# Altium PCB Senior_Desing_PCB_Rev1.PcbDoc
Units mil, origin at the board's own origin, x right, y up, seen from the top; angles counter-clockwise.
Board outline 6000 x 4000 mil, 2 copper layers (Top Layer, Bottom Layer); 40 components, 31 nets, 152 pads, 0 vias.
Unrouted connection lines stored in the file: 76.
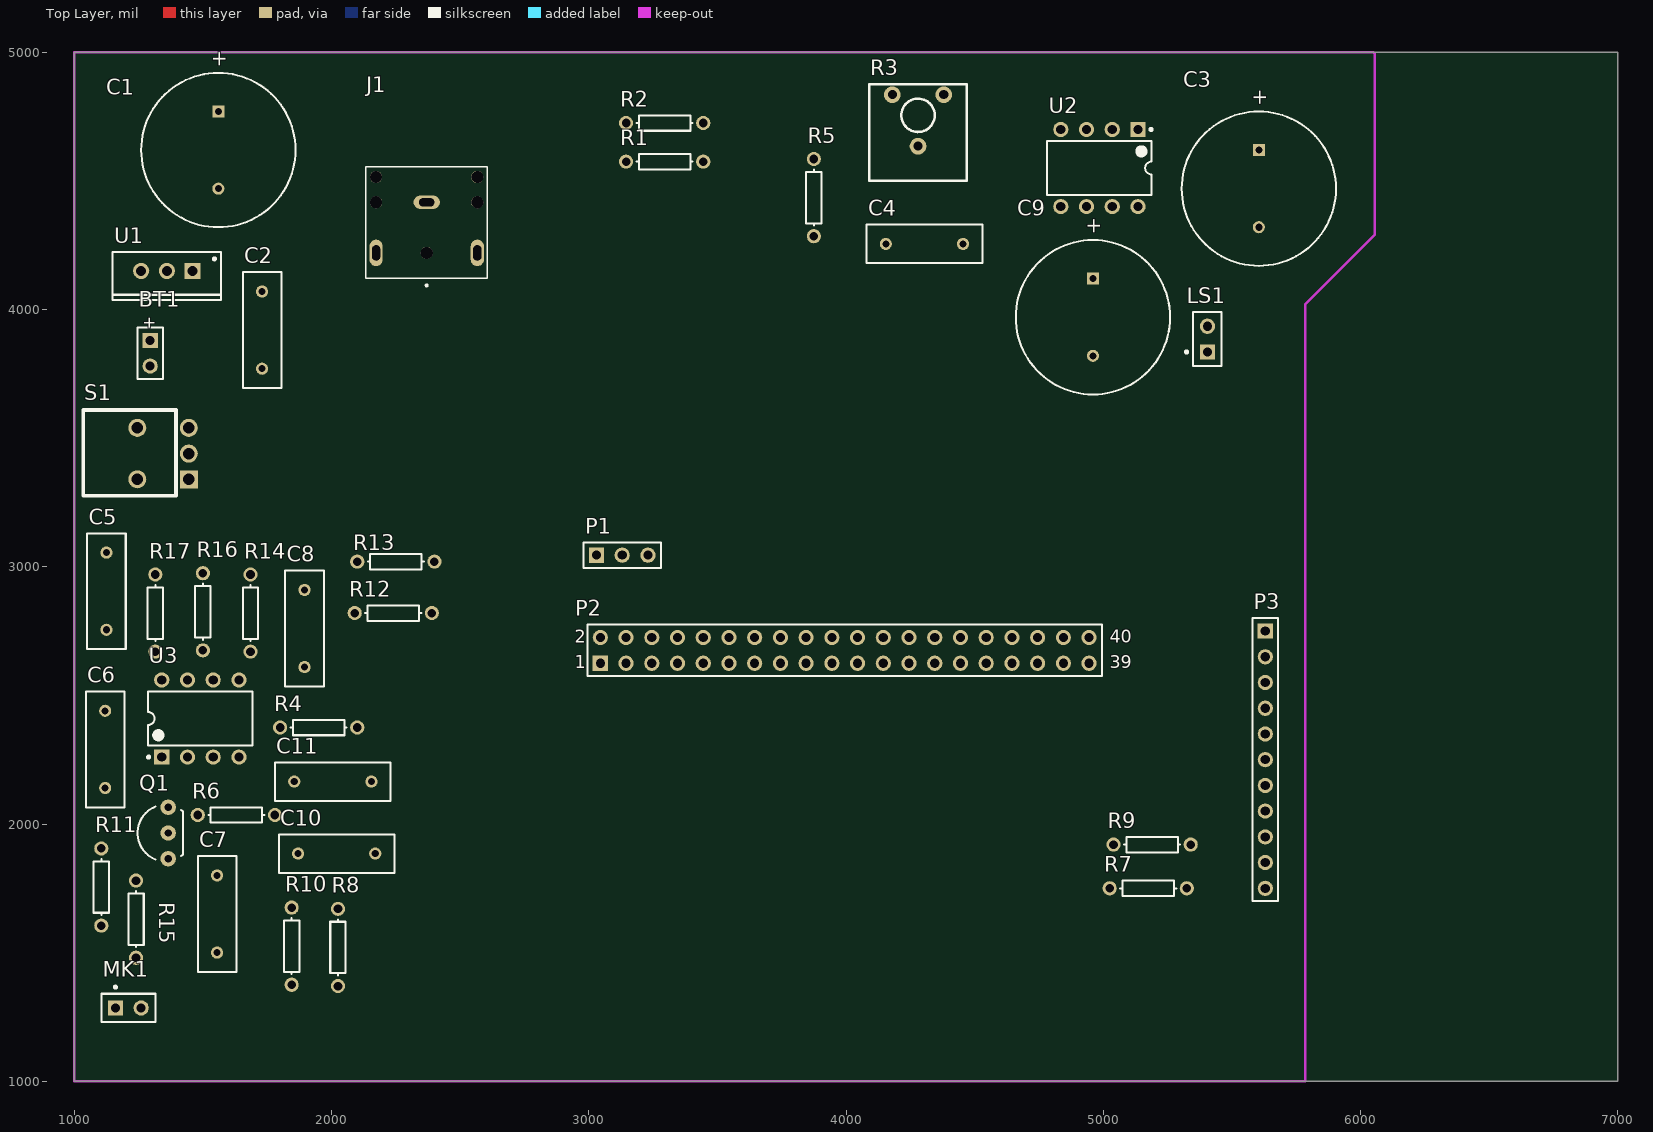
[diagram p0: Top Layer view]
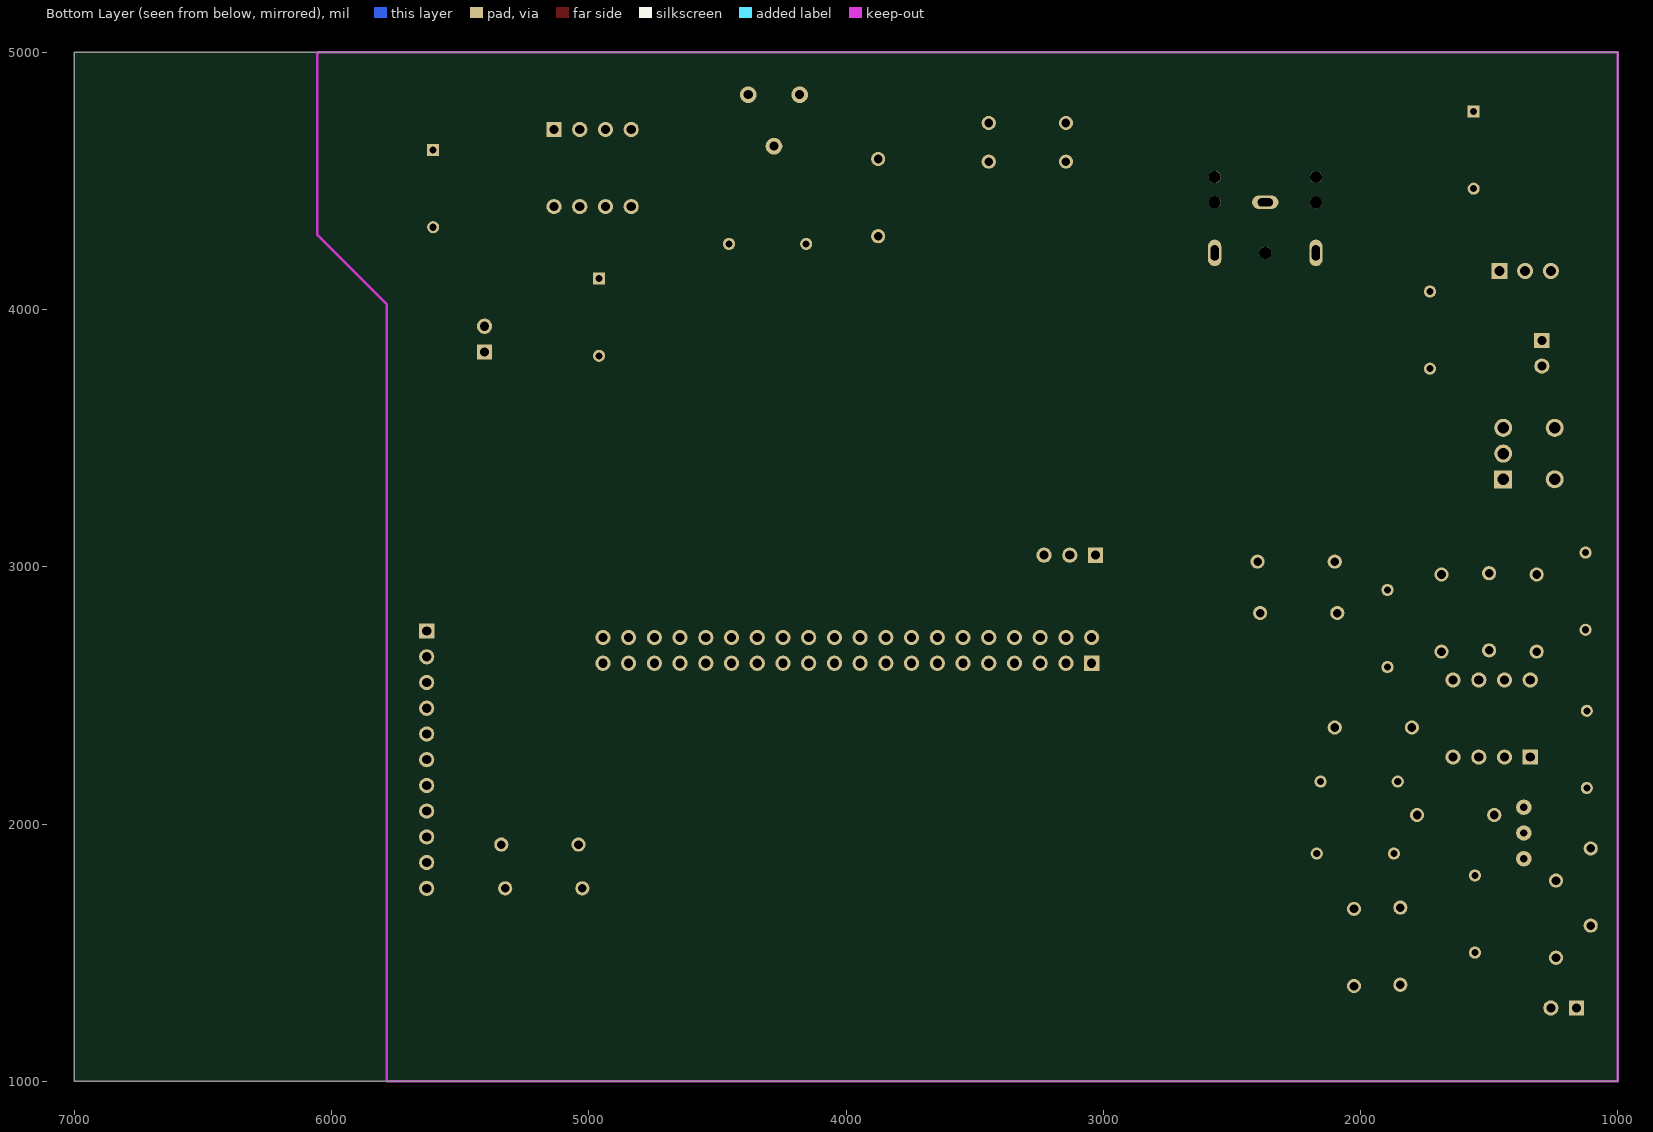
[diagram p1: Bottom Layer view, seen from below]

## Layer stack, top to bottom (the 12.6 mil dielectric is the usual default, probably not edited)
Top Solder: solder mask 0.4, Solder Resist, Dk 3.5
Top Layer: signal copper 1.4
Dielectric 1: dielectric 12.6, FR-4, Dk 4.8
Bottom Layer: signal copper 1.4
Bottom Solder: solder mask 0.4, Solder Resist, Dk 3.5

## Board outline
1000,1000 7000,1000 7000,5000 1000,5000

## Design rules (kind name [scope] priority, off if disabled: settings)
Clearance [All] p1: gap=10 ignorepadtopadclearanceinfootprint=FALSE except(0: Arc-Hole Track-Hole SMDPad-Hole THPad-Hole Via-Hole Fill-Hole Poly-Hole Region-Hole Text-Hole)
PolygonConnect [All] p1: connectstyle=Relief reliefconductorwidth=10 reliefentries=4 polygonreliefangle="90 Angle" airgapwidth=10
RoutingVias [All] p1: holewidth=28 width=50 viastyle="Through Hole" minholewidth=28 minwidth=50 maxholewidth=28 maxwidth=50
SolderMaskExpansion [All] p1: expansion=4 istentingtop=FALSE
Width [All] p1: maxlimit=10 minlimit=10 preferedwidth=10
30 further rules are at their usual default settings.

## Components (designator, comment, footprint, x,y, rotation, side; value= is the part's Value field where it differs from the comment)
BT1 "Battery" BAT-2 1295,3830 r270 top
C1 "Cap Pol1" RB7.6-15 1560,4620 r90 top value=100pF
C2 "Cap" RAD-0.3 1730,3920 r270 top value=0.47uF
C3 "Cap Pol1" RB7.6-15 5605,4470 r90 top value=100uF
C4 "Cap" RAD-0.3 4305,4255 r0 top value=0.05uF
C5 "Cap" RAD-0.3 1125,2905 r90 top value=0.1uF
C6 "Cap" RAD-0.3 1120,2290 r90 top value=0.33uF
C7 "Cap" RAD-0.3 1555,1650 r90 top value=220nF
C8 "Cap" RAD-0.3 1895,2760 r90 top value=220nF
C9 "Cap Pol1" RB7.6-15 4960,3970 r90 top value=220uF
C10 "Cap" RAD-0.3 2020,1885 r0 top value=10uF
C11 "Cap" RAD-0.3 2005,2165 r0 top value=0.1uF
J1 "SJ1-3523N" CUI_SJ1-3523N 2370,4416.85 r180 top
LS1 "Speaker" PIN2 5405,3835 r90 top
MK1 "Mic1" PIN2 1160,1285 r0 top
P1 "Screen" HDR1X3 3030,3045 r0 top
P2 "PI 5" HDR2X20 3045,2625 r0 top
P3 "CODEC WM8731" HDR1X11 5630,2750 r270 top
Q1 "2N3904" TO92C 1365,1865 r180 top
R1 "Res1" AXIAL-0.3 3295,4575 r180 top value=1K
R2 "Res1" AXIAL-0.3 3295,4725 r180 top value=1K
R3 "RPot_3" "POT OFFSET 200" 4380,4835 r180 top value=10K
R4 "Res1" AXIAL-0.3 1950,2375 r180 top value=100K
R5 "Res1" AXIAL-0.3 3875,4435 r270 top value=10
R6 "Res1" AXIAL-0.3 1630,2035 r180 top value=100K
R7 "Res1" AXIAL-0.3 5175,1750 r180 top value=1K
R8 "Res1" AXIAL-0.3 2025,1520 r270 top value=4.7K
R9 "Res1" AXIAL-0.3 5190,1920 r180 top value=1K
R10 "Res1" AXIAL-0.3 1845,1525 r270 top value=100K
R11 "Res1" AXIAL-0.3 1105,1755 r270 top value=2.2K
R12 "Res1" AXIAL-0.3 2240,2820 r180 top value=22K
R13 "Res1" AXIAL-0.3 2250,3020 r180 top value=10k
R14 "Res1" AXIAL-0.3 1685,2820 r270 top value=10K
R15 "Res1" AXIAL-0.3 1240,1630 r90 top value=1K
R16 "Res1" AXIAL-0.3 1500,2825 r270 top value=1K
R17 "Res1" AXIAL-0.3 1315,2820 r90 top value=1K
S1 "SW-SPDT" "SW DPST jameco" 1446.89,3437.64 r270 top
U1 "LM2940CT-3.3" T03B 1360,4150 r180 top
U2 "LM386N-1" DIP-8 4985,4550 r270 top
U3 "LT1632CN8" DIP-8 1490,2410 r90 top

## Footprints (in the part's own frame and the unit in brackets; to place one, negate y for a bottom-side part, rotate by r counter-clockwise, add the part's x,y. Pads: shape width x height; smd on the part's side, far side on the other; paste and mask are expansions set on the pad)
AXIAL-0.3 [mm] "Axial Device, Thru-Hole; 2 Leads; 0.3 in Pin Spacing"
  round 1.4 hole 0.85: 1(-3.81,0) 2(3.81,0)
  silkscreen extent -2.77,-0.76 2.77,0.76
BAT-2 [mm] "Battery; 2 Leads"
  rect 1.5x1.5 hole 0.9: 1(-1.27,0)
  round 1.5 hole 0.9: 2(1.27,0)
  silkscreen extent -2.54,-1.27 2.54,1.27
CUI_SJ1-3523N [mm]
  oval 2.616x1.308 hole 0.8 slot 1.5 at 0 deg: 1(0,0)
  oval 1.308x2.616 hole 0.8 slot 1.5 at 90 deg: 2(5,5) 3(-5,5)
  round 1.2 hole 1.2 unplated: ""(-5,-2.5) ""(-5,0) ""(0,5) ""(5,-2.5) ""(5,0)
  silkscreen extent -6,-3.5 6,8.3, body extent -6,0 6,14.3, height 3.01
DIP-8 [mm]
  rect 1.5x1.5 hole 0.9: 1(-3.81,3.81)
  round 1.5 hole 0.9: 2(-3.81,1.27) 3(-3.81,-1.27) 4(-3.81,-3.81) 5(3.81,-3.81) 6(3.81,-1.27) 7(3.81,1.27) 8(3.81,3.81)
  silkscreen extent -3.93,-5.15 2.65,5.24, body extent -3.6,-5.15 3.6,5.15, height 5.08
HDR1X3 [mm] "Connector; Header; 3 Position"
  rect 1.5x1.5 hole 0.9: 1(0,0)
  round 1.5 hole 0.9: 2(2.54,0) 3(5.08,0)
  silkscreen extent -1.27,-1.27 6.35,1.27
HDR1X11 [mm] "Connector; Header; 11 Position"
  rect 1.5x1.5 hole 0.9: 1(0,0)
  round 1.5 hole 0.9: 2(2.54,0) 3(5.08,0) 4(7.62,0) 5(10.16,0) 6(12.7,0) 7(15.24,0) 8(17.78,0) 9(20.32,0) 10(22.86,0) 11(25.4,0)
  silkscreen extent -1.27,-1.27 26.67,1.27
HDR2X20 [mm] "Connector; Header; 20x2 Position"
  rect 1.5x1.5 hole 0.9: 1(0,0)
  round 1.5 hole 0.9: 2(0,2.54) 3(2.54,0) 4(2.54,2.54) 5(5.08,0) 6(5.08,2.54) 7(7.62,0) 8(7.62,2.54) 9(10.16,0) 10(10.16,2.54) 11(12.7,0) 12(12.7,2.54) 13(15.24,0) 14(15.24,2.54) 15(17.78,0) 16(17.78,2.54) 17(20.32,0) 18(20.32,2.54) 19(22.86,0) 20(22.86,2.54) 21(25.4,0) 22(25.4,2.54) 23(27.94,0) 24(27.94,2.54) 25(30.48,0) 26(30.48,2.54) 27(33.02,0) 28(33.02,2.54) 29(35.56,0) 30(35.56,2.54) 31(38.1,0) 32(38.1,2.54) 33(40.64,0) 34(40.64,2.54) 35(43.18,0) 36(43.18,2.54) 37(45.72,0) 38(45.72,2.54) 39(48.26,0) 40(48.26,2.54)
  silkscreen extent -1.27,-1.27 49.53,3.81
PIN2 [mm] "Photosensitive Diode; 2 Leads"
  rect 1.5x1.5 hole 0.9: 1(0,0)
  round 1.5 hole 0.9: 2(2.54,0)
  silkscreen extent -1.4,-1.4 3.94,2.17
"POT OFFSET 200" [mil]
  round 65 hole 35: 1(0,0) 2(100,200) 3(200,0)
  silkscreen extent -90,-40 290,335
RAD-0.3 [mm] "Radial Cap, Thru-Hole; 2 Leads; 0.3 in Pin Spacing"
  round 1.2 hole 0.7: 1(-3.81,0) 2(3.81,0)
  silkscreen extent -5.71,-1.91 5.71,1.91
RB7.6-15 [mm] "Polarized Capacitor (Radial); 2 Leads"
  rect 1.2x1.2 hole 0.7: 1(3.81,0)
  round 1.2 hole 0.7: 2(-3.81,0)
  silkscreen extent -7.62,-7.62 7.62,7.62
"SW DPST jameco" [mil]
  rect 70x70 hole 45: 1(97.64,-1.89)
  round 70 hole 45: 2(-2.36,-1.89) 3(-102.36,-1.89) 4(-102.36,-201.89) 5(97.64,-201.89)
  silkscreen extent -172,-412 162,-52
T03B [mm]
  rect 1.6x1.6 hole 1: 1(-2.54,0)
  round 1.6 hole 1: 2(0,0) 3(2.54,0)
  silkscreen extent -5.35,-1.85 5.35,2.85, body extent -5.4,-1.9 5.4,2.9, height 19.4
TO92C [mil]
  round 60 hole 28: 1(0,0) 2(0,-100) 3(0,-200)
  silkscreen extent -58,-203 119,3

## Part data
BT1: "Multicell Battery"
C1 C3 C9: "Polarized Capacitor (Radial)"
C2 C4 C5 C6 C7 C8 C10 C11: "Capacitor"
J1: "3.5 mm, Stereo, Right Angle, Through Hole, 3 Conductors, 0 Internal Switches, Audio Jack Connector", Package=None
LS1: "Loudspeaker"
MK1: "Microphone"
P1: library part "Header 3", "Header, 3-Pin"
P2: library part "Header 20X2", "Header, 20-Pin, Dual row"
P3: library part "Header 11", "Header, 11-Pin"
Q1: "NPN General Purpose Amplifier"
R1 R2 R4 R5 R6 R7 R8 R9 R10 R11 R12 R13 R14 R15 R16 R17: "Resistor"
R3: library part RPot, "Potentiometer"
S1: "SPDT Subminiature Toggle Switch, Right Angle Mounting, Vertical Actuation"
U1: library part LM2940CT-5.0, "1A Low Dropout Regulator, 3-pin TO-220", Manufacturer="National Semiconductor", PackageTopMarking="NSUZXYTTE#*LM2940CT*-5.0 P+", PowerWise=N
U2: "Low-Voltage Audio Power Amplifier", PackageDocument=Sep-1997
U3: "45MHz, 45V/µs, Dual Rail-to-Rail Input and Output Precision Operational Amplifier"

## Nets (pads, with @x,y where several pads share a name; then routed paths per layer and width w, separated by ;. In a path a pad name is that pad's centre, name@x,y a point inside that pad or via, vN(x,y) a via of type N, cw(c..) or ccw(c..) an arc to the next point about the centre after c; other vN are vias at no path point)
+3V3_PI: P2.17 P3.8
+5V_ANA: C1.1 C5.1 R8.2 R10.2 R11.1 R16.1 U1.3 U3.8
+5V_PI: P1.1 P2.2
+9V: BT1.1 C3.1 S1.2 U2.6
ADCL_DACL: P2.35 P3.4 P3.5
AGND: BT1.2 C1.2 C2.1 C3.2 C5.2 C10.1 C11.1 J1.1 LS1.2 MK1.2 P2.9 R3.3 R5.1 R12.1 R13.1 R15.1 R17.2 U1.2 U2.2 U2.4 U3.4
DGND: P1.3 P2.6 P3.9
I2C_SCL: P2.5 P3.7
I2C_SDA: P2.3 P3.6
LLINEIN: P3.10 R9.2
MISO: P2.38 P3.2
MOSI: P2.40 P3.3
NetC2_2: C2.2 S1.3 U1.1
NetC4_1: C4.1 R5.2
NetC4_2: C4.2 C9.1 U2.5
NetC6_1: C6.1 Q1.3 R8.1
NetC6_2: C6.2 R4.2 U3.3
NetC7_1: C7.1 MK1.1 R11.2
NetC7_2: C7.2 Q1.2 R10.1 R12.2
NetC8_1: C8.1 R6.2 U3.1
NetC8_2: C8.2 R7.1 R9.1 R13.2
NetC9_2: C9.2 LS1.1
NetC10_2: C10.2 C11.2 R4.1 R14.2 R16.2 R17.1
NetJ1_2: J1.2 R2.2
NetJ1_3: J1.3 R1.2
NetQ1_1: Q1.1 R15.2
NetR1_1: R1.1 R2.1 R3.1
NetR3_2: R3.2 U2.3
NetR6_1: R6.1 R14.1 U3.2
RLINEIN: P3.11 R7.2
SCK: P2.12 P3.1
pads on no net: J1. P1.2 P2.1 P2.4 P2.7 P2.8 P2.10 P2.11 P2.13 P2.14 P2.15 P2.16 P2.18 P2.19 P2.20 P2.21 P2.22 P2.23 P2.24 P2.25 P2.26 P2.27 P2.28 P2.29 P2.30 P2.31 P2.32 P2.33 P2.34 P2.36 P2.37 P2.39 S1.1 S1.4 S1.5 U2.1 U2.7 U2.8 U3.5 U3.6 U3.7

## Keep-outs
Keep-Out Layer:
  lines w10: 1000,1000 5785,1000 5785,4020 6055,4290 6055,4995 6050,5000 1000,5000 1000,1000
